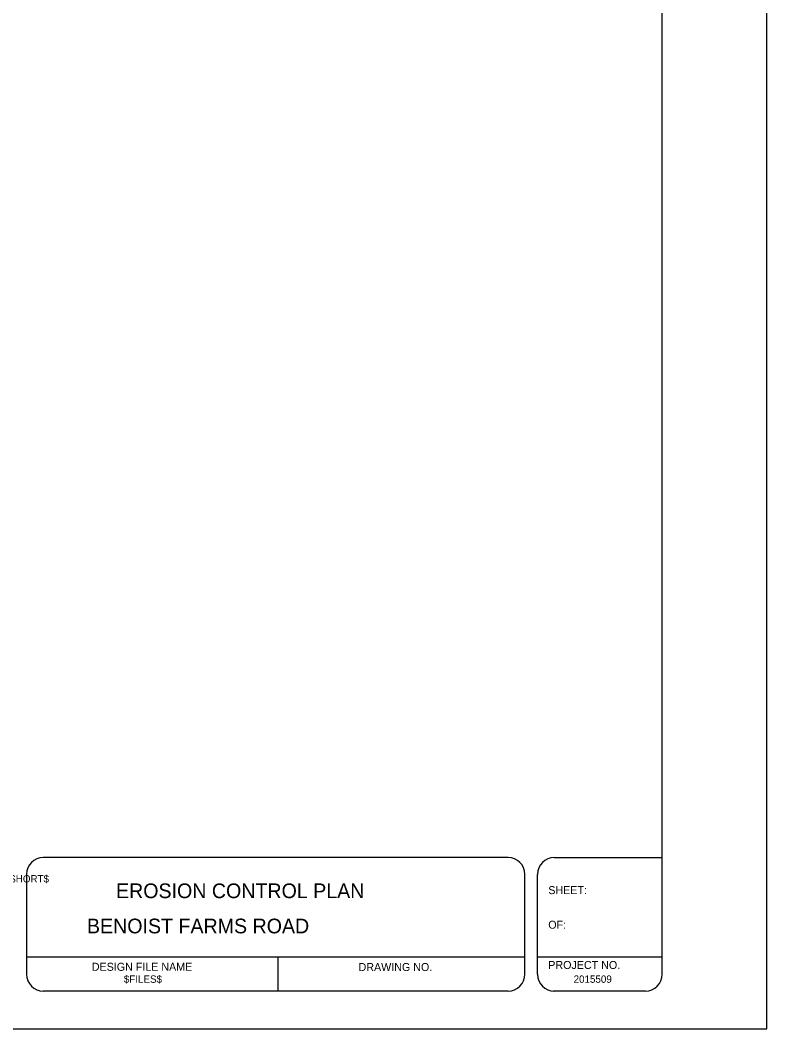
# Model space of a CAD drawing. Extents: x -0.6 to 16, y -0.9 to 9.7.
# Drawn here: x 12.02 to 15.95, y -0.9 to 4.4 of the extents above; entities that cross this region are included whole.
import ezdxf

# ---------------------------------------------------------------- set-up
doc = ezdxf.new("R2010")
doc.units = 0
for name, color, linetype in [('Default', 7, 'Continuous'), ('PlotBorder_dp', 7, 'Continuous'), ('TextMinor', 7, 'Continuous')]:
    doc.layers.add(name, color=color, linetype=linetype)

msp = doc.modelspace()

# ---------------------------------------------------------------- linework, layer by layer
at = {"layer": 'Default'}
for p, q in [((15.4, -0.6133), (15.4, 9.5065)), ((14.5898, 0), (12.146, 0)), ((14.8324, 0), (15.4, 0)), ((12.0578, -0.0882), (12.0578, -0.6131)), ((14.678, -0.6135), (14.678, -0.0884)), ((14.7442, -0.6135), (14.7442, -0.0884)), ((14.6769, -0.5241), (12.0568, -0.5241)), ((13.3801, -0.7005), (13.3801, -0.5241)), ((15.4, -0.5241), (14.7475, -0.5241)), ((14.5898, -0.7014), (12.146, -0.7014)), ((15.3118, -0.7015), (14.8271, -0.7015))]:
    msp.add_line(p, q, dxfattribs=at)
for centre, major_axis, start_param, end_param in [((12.146, -0.0882), (0, 0.0882), 0, 1.570796), ((14.5898, -0.0884), (0, 0.0882), 4.712389, 6.283185), ((14.8324, -0.0884), (0, -0.0882), 3.141593, 4.712389), ((12.146, -0.6131), (0, -0.0882), 4.712389, 6.283185), ((14.5898, -0.6131), (0, 0.0882), 3.141593, 4.712389), ((14.8324, -0.6135), (0, -0.0882), 4.712389, 6.283185), ((15.3118, -0.6133), (0, -0.0882), 0, 1.570796)]:
    msp.add_ellipse(centre, major_axis=major_axis, ratio=0.999927, start_param=start_param, end_param=end_param, dxfattribs=at)
at = {"layer": 'PlotBorder_dp'}
msp.add_lwpolyline([(-0.55, -0.9), (15.95, -0.9), (15.95, 9.7), (-0.55, 9.7)], close=True, dxfattribs=at)

# ---------------------------------------------------------------- texts
at = {"layer": 'Default'}
for s, height, p in [('EROSION CONTROL PLAN', 0.077091, (12.5281, -0.2133)), ('SHEET:', 0.04207, (14.8009, -0.1922)), ('   BENOIST FARMS ROAD   ', 0.077091, (12.2895, -0.3982)), ('OF:', 0.04207, (14.8009, -0.374)), ('DESIGN FILE NAME', 0.042066, (12.4009, -0.5951)), ('DRAWING NO.', 0.042066, (13.8035, -0.5964)), ('PROJECT NO.', 0.042066, (14.8009, -0.5856)), ('$FILES$', 0.03855, (12.5694, -0.6581)), ('2015509', 0.03855, (14.9341, -0.6581))]:
    msp.add_text(s, height=height, dxfattribs=at).set_placement(p)
at = {"layer": 'TextMinor'}
msp.add_text('$SCALESHORT$', height=0.038546, dxfattribs=at).set_placement((11.7691, -0.1311))

doc.saveas('drawing.dxf')
